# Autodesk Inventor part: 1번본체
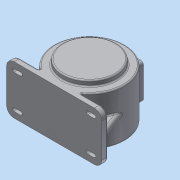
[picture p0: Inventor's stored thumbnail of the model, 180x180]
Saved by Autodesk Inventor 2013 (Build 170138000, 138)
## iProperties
Created: 2015-06
Part Number: 1번본체
Material: 알루미늄 6061
Document SubType Name: Modeling
Designer: dgall
Density: 2.71 g/cm^3
Mass: 3271.77 g
Surface Area: 2307.15 cm^2
Volume: 1207.3 cm^3
Author: dgall
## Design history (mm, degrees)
sketch "스케치1"
  geometry: L1 (0, 59)-(0, -59); L2 (0, 59)-(85, 59); L3 (85, 59)-(85, -59); L4 (85, -59)-(0, -59); L5 (0, 51)-(77, 51); L6 (77, 51)-(77, -51); L7 (77, -51)-(0, -51); 2 further points
  constraints: 14 end point, 4 perpendicular, 2 coincident, 2 parallel, 2 point on line, 1 midpoint, 1 vertical
  dimensions: "d0" = 118 distance of L1.start L1.end; "d2" = 170 diameter of L3 L1; "d3" = 154 diameter of L6 L1; "d4" = 8 distance between parallel lines of L5 L2; "d5" = 8 distance between parallel lines of L4 L7 (= d4)
revolve "회전1" sketch "스케치1" stored, may be unused: angle "d6" = 90 deg
sketch "스케치2"
  geometry: C1 r 85 at (0, 0) reference; C2 r 65 at (0, 0)
  constraints: 1 centre point, 1 coincident
  dimensions: "d7" = 130 diameter of C2
extrude "돌출1" join sketch "스케치2" distance "d9" = 3; taper "d10" = 0 deg
sketch "스케치3"
  geometry: C1 r 85 at (0, 0) reference; C2 r 65 at (0, 0)
  constraints: 1 centre point, 1 coincident
  dimensions: "d11" = 130 diameter of C2
extrude "돌출2" join sketch "스케치3" distance "d13" = 13; taper "d14" = 0 deg
sketch "스케치4"
  geometry: L1 (115, -71)-(115, -85); L2 (115, -85)-(-115, -85); L3 (-115, -85)-(-115, -71); L4 (-115, -71)-(-46.733, -71); L5 (46.733, -71)-(115, -71); C1 r 65 at (0, 0) reference; A1 r 85 centre (0, 0) between (-46.733, -71) and (46.733, -71) reference
  constraints: 10 end point, 3 parallel, 2 horizontal, 2 perpendicular, 2 point on circle, 1 collinear, 1 horizontal alignment
  dimensions: "d15" = 14 distance of L2.end L3.end; "d17" = 85 distance from line of L2 C1.centre; "d18" = 230 distance of L1.end L2.end
extrude "돌출3" join sketch "스케치4" distance "d19" = 118; taper "d20" = 0 deg
node "작업 평면1"
sketch "스케치5"
  geometry: L1 (-157.5, 101.5)-(-72.5, 101.5); L2 (-72.5, 101.5)-(-72.5, 16.5); L3 (-72.5, 16.5)-(-157.5, 16.5); L4 (-157.5, 16.5)-(-157.5, 101.5); L5 (0, 118)-(-230, 118) reference; L6 (-230, 0)-(-230, 118) reference; 3 further points
  constraints: 8 end point, 2 midpoint, 2 parallel, 1 horizontal, 1 horizontal alignment, 1 perpendicular, 1 vertical alignment
  dimensions: "d22" = 85 distance of L1.start L1.end; "d24" = 85 distance of L3.end L1.start
extrude "돌출4" join sketch "스케치5" stored distance "d25" = 118; taper "d26" = 0 deg
hole "구멍1" diameter "d29" = 95; stored, may be unused: countersink angle "d33" = 90 deg, drill point angle "d35" = 0 deg; dims "d27" = 10, "d28" = 10, "d30" = 6, "d31" = 4, "d32" = 2, "d34" = 11
sketch "스케치6"
  geometry: C1 r 77 at (0, 0) reference; C2 r 31 at (0, 0)
  constraints: 1 centre point, 1 coincident
  dimensions: "d36" = 62 diameter of C2
extrude "돌출5" join sketch "스케치6" distance "d38" = 3.5; taper "d39" = -25 deg
hole "구멍2" diameter "d42" = 30; stored, may be unused: countersink angle "d46" = 90 deg, drill point angle "d48" = 0 deg; dims "d40" = 10, "d41" = 10, "d43" = 6, "d44" = 47, "d45" = 14, "d47" = 17
fillet "모깎기1" dims "d58" = 7
fillet "모깎기2" dims "d59" = 18
node "작업 평면2"
sketch "스케치7"
  geometry: L1 (-97, -71)-(-46.733, -71) reference; L2 (-115, -71)-(-97, -71) reference; L3 (-84.87, -4.703)-(-109, -71); A1 r 85 centre (0, 0) between (46.733, -71) and (-46.733, -71) reference; 1 further point
  constraints: 2 end point, 1 point on circle, 1 point on line
  dimensions: "d61" = 110 deg angle of L2 L3; "d62" = 6 distance of L3.end L2.start
feature "리브1" sketch "스케치7" dims "d63" = 1, "d64" = 15, "d65" = 0, "d66" = 0, "d67" = 1, "d68" = 1
fillet "모깎기3" dims "d69" = 7.5
sketch "스케치8"
  geometry: C1 r 47.5 at (0, 0) reference; 1 further point
  constraints: 1 vertical alignment
  dimensions: "d70" = 55 distance of C1.centre point (0, 55)
sketch "스케치10"
  geometry: L1 (-93.467, -66.5)-(-147.752, -66.5) reference; L2 (-147.752, -51.5)-(-93.467, -51.5) reference; L3 (-93.467, 0)-(-93.467, -51.5) reference; L4 (-143.733, 0)-(-93.467, 0) reference; L5 (-161.733, -18)-(-161.733, -100) reference; L6 (-93.467, -118)-(-143.733, -118) reference; L7 (-93.467, -66.5)-(-93.467, -118) reference; L8 (-127.733, -109)-(-143.733, -109); L9 (-143.733, -91)-(-127.733, -91); L10 (-143.733, -104)-(-127.733, -104); L11 (-127.733, -96)-(-143.733, -96); A1 r 18 centre (-143.733, -18) between (-143.733, 0) and (-161.733, -18) reference; A2 r 18 centre (-143.733, -100) between (-161.733, -100) and (-143.733, -118) reference; A3 r 9 centre (-143.733, -100) between (-143.733, -91) and (-143.733, -109); A4 r 9 centre (-127.733, -100) between (-127.733, -109) and (-127.733, -91); A5 r 4 centre (-127.733, -100) between (-127.733, -104) and (-127.733, -96); A6 r 4 centre (-143.733, -100) between (-143.733, -96) and (-143.733, -104); 2 further points; 1 other entity
  constraints: 8 end point, 8 point on circle, 4 centre point, 4 tangent, 2 parallel, 1 coincident, 1 horizontal alignment, 1 perpendicular, 4 other
  dimensions: "d78" = 16 distance of A2.centre A4.centre; "d79" = 18 distance between parallel lines of L9 L8; "d80" = 8 distance between parallel lines of L11 L10
  node "투영된 루프1"
extrude "돌출6" join sketch "스케치10" distance "d81" = 3; taper "d82" = 0 deg
extrude "돌출7" cut sketch "스케치10" stored distance "d83" = 30; taper "d84" = 0 deg
node "작업 평면4"
  node "작업 평면3"
sketch "스케치11"
  geometry: 2 further points
  constraints: 1 coincident, 1 other
feature "엠보싱1" sketch "스케치11" dims "d86" = 0.5, "d87" = 0
hole "구멍5" sketch "스케치8" diameter "d88" = 3.242; stored, may be unused: countersink angle "d92" = 90 deg, drill point angle "d94" = 0 deg; dims "d89" = 10, "d90" = 47, "d91" = 14, "d93" = 11
chamfer "모따기1" distance "d99" = 1; stored, may be unused: second distance "d100" = 2, angle "d101" = 45 deg
chamfer "모따기2" distance "d102" = 1; stored, may be unused: second distance "d103" = 2, angle "d104" = 45 deg
fillet "모깎기5" dims "d105" = 0.3
fillet "모깎기6" dims "d106" = 3
fillet "모깎기7" dims "d107" = 3
fillet "모깎기8" dims "d111" = 2
fillet "모깎기9" dims "d112" = 3
sketch "스케치12"
  geometry: L1 (80.522, 42.5)-(91, 42.5) reference; L2 (91, 42.5)-(91, 35.5) reference; L3 (91, -42.5)-(80.522, -42.5) reference; L4 (88, 42.5)-(88, -42.5); L5 (-85, -45)-(-85, -37) reference; L6 (91, 35.5)-(91, -35.5) reference; L7 (91, -35.5)-(91, -42.5) reference; 1 further point
  constraints: 2 end point, 2 point on line, 1 perpendicular
  dimensions: "d113" = 173 distance between parallel lines of L5 L4
extrude "돌출8" cut sketch "스케치12" stored distance "d114" = 10; taper "d115" = 0 deg
hole "구멍6" diameter "d118" = 70; stored, may be unused: countersink angle "d122" = 90 deg, drill point angle "d124" = 0 deg; dims "d116" = 42.5, "d117" = 42.5, "d119" = 6, "d120" = 4, "d121" = 2, "d123" = 8
sketch "스케치13"
  geometry: A1 r 7 centre (0, 7) between (-7, 7) and (0, 0) reference; A2 r 7 centre (71, 7) between (71, 0) and (78, 7) reference; A3 r 7 centre (71, 78) between (78, 78) and (71, 85) reference; A4 r 7 centre (0, 78) between (0, 85) and (-7, 78) reference
hole "구멍7" sketch "스케치13" at (0, 7), (71, 7), (71, 78), (0, 78) diameter "d125" = 3.242; stored, may be unused: countersink angle "d129" = 90 deg, drill point angle "d131" = 118 deg; dims "d126" = 10, "d127" = 4, "d128" = 2, "d130" = 13
chamfer "모따기4" distance "d132" = 1; stored, may be unused: second distance "d133" = 2, angle "d134" = 45 deg
fillet "모깎기10" dims "d135" = 3
node "솔리드1"
mirror "대칭1"
mirror "대칭2"
mirror "대칭3"
pattern_circular "원형 패턴1" dims angle "d96" = 360 deg
node "작업축1"
other parameters: "d21" = -176, "d60" = -59, "d85" = -65 deg
